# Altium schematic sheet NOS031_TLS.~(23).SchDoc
size A4
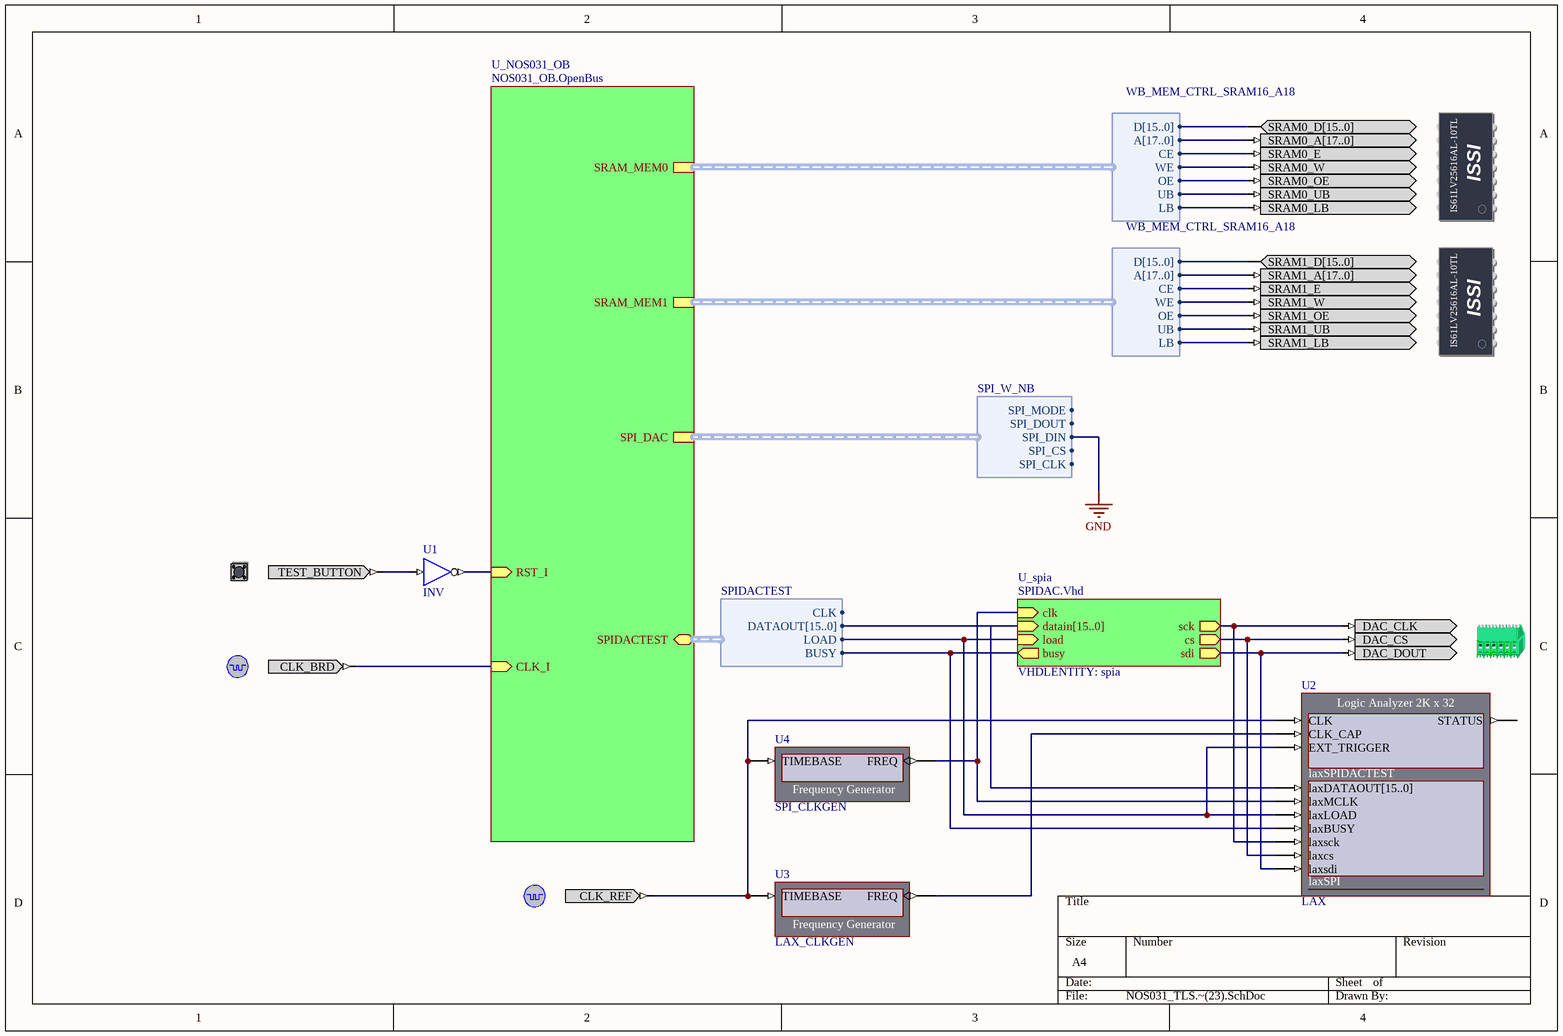
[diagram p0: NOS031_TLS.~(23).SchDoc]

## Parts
(Parts that share a designator on the sheet are numbered #1, #2 ... from top to bottom, then left to right.)
?#1  SRAM0  (value not drawn)
?#2  SRAM1  (value not drawn)
?#3  TEST_BUTTON  (value not drawn)
?#4  ADCDAC  (value not drawn)
?#5  CLOCK_BOARD  (value not drawn)
?#6  CLOCK_REFERENCE  (value not drawn)
U1  INV
U2  LAX
U3  LAX_CLKGEN
U4  SPI_CLKGEN

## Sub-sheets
U_NOS031_OB = NOS031_OB.OpenBus: SRAM_MEM0 (harness WB_MEM_CTRL_SRAM16_A18), SRAM_MEM1 (harness WB_MEM_CTRL_SRAM16_A18), SPI_DAC (harness SPI_W_NB), RST_I (in), CLK_I (in), SPIDACTEST (harness SPIDACTEST)
U_spia = SPIDAC.Vhd: busy (out), clk (in), cs (out), datain[15..0] (in), load (in), sck (out), sdi (out)  | VHDLENTITY: spia

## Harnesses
SPI_W_NB: SPI_CLK, SPI_CS, SPI_DIN, SPI_DOUT, SPI_MODE
WB_MEM_CTRL_SRAM16_A18: D[15..0], A[17..0], CE, WE, OE, UB, LB
SPIDACTEST: DATAOUT[15..0], LOAD, BUSY, CLK

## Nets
GND_BUS[9..0]: U2.Set0_Spare[9..0]
GND_BUS[31..0]: U2.Set1_Spare[31..0]
Net?#1_SRAM0_E: ?#1.SRAM0_E ; sheet U_NOS031_OB/SRAM_MEM0.CE
Net?#1_SRAM0_LB: ?#1.SRAM0_LB ; sheet U_NOS031_OB/SRAM_MEM0.LB
Net?#1_SRAM0_OE: ?#1.SRAM0_OE ; sheet U_NOS031_OB/SRAM_MEM0.OE
Net?#1_SRAM0_UB: ?#1.SRAM0_UB ; sheet U_NOS031_OB/SRAM_MEM0.UB
Net?#1_SRAM0_W: ?#1.SRAM0_W ; sheet U_NOS031_OB/SRAM_MEM0.WE
Net?#2_SRAM1_E: ?#2.SRAM1_E ; sheet U_NOS031_OB/SRAM_MEM1.CE
Net?#2_SRAM1_LB: ?#2.SRAM1_LB ; sheet U_NOS031_OB/SRAM_MEM1.LB
Net?#2_SRAM1_OE: ?#2.SRAM1_OE ; sheet U_NOS031_OB/SRAM_MEM1.OE
Net?#2_SRAM1_UB: ?#2.SRAM1_UB ; sheet U_NOS031_OB/SRAM_MEM1.UB
Net?#2_SRAM1_W: ?#2.SRAM1_W ; sheet U_NOS031_OB/SRAM_MEM1.WE
Net?#3_TEST_BUTTON: ?#3.TEST_BUTTON U1.I
Net?#4_DAC_CLK: ?#4.DAC_CLK U2.laxsck ; sheet U_spia/sck
Net?#4_DAC_CS: ?#4.DAC_CS U2.laxcs ; sheet U_spia/cs
Net?#4_DAC_DOUT: ?#4.DAC_DOUT U2.laxsdi ; sheet U_spia/sdi
Net?#5_CLK_BRD: ?#5.CLK_BRD ; sheet U_NOS031_OB/CLK_I
Net?#6_CLK_REF: ?#6.CLK_REF U2.CLK U3.TIMEBASE U4.TIMEBASE
NetU1_O: U1.O ; sheet U_NOS031_OB/RST_I
NetU2_CLK_CAP: U2.CLK_CAP U3.FREQ
NetU2_EXT_TRIGGER: U2.EXT_TRIGGER U2.laxLOAD ; sheet U_spia/load, sheet U_NOS031_OB/SPIDACTEST.LOAD
NetU2_laxBUSY: U2.laxBUSY ; sheet U_spia/busy, sheet U_NOS031_OB/SPIDACTEST.BUSY
NetU2_laxMCLK: U2.laxMCLK U4.FREQ ; sheet U_spia/clk

Not connected (* = marked no-connect by the designer): ?#1 SRAM0_A[17..0] SRAM0_D[15..0]; ?#2 SRAM1_A[17..0] SRAM1_D[15..0]; U2 laxDATAOUT[15..0] STATUS

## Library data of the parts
?#1 = SRAM0: Free Static RAM - Daughterboard; PortComponent: True
?#2 = SRAM1: Free Static RAM - Daughterboard; PortComponent: True
?#3 = TEST_BUTTON: Test / Reset Button; PortComponent: True
?#4 = DAC: Digital Analog Converter; PortComponent: True
?#5 = CLOCK_BOARD: Global System Clock Supply; PortComponent: True
?#6 = CLOCK_REFERENCE: Global System Clock Reference Supply; PortComponent: True
U1 = INV: Inverter; FunctionalClass: Logic Primitive; ArchiveName: GENERIC; VHDLIB_SIM: GENERIC_LIB
U2 = LAX: Configurable Logic Analyzer; NEXUS_CORE: Instrument; NEXUS_JTAG_DEVICE: True; NEXUS_JTAG_ORDER: 0; ConfiguratorName: LogicAnalyser; ConfigurationParameters: {}Version[1.0]{}CaptureWidth[32]{}MemorySize[2K]{}ExtAddrWidth[10]{}Set0[laxSPIDACTEST]{}Set0_Signal0[laxDATAOUT(15..0)]{}Style_Set0_Signal0[Default]{}Set0_Signal1[laxMCLK]{}Style_Set0_Signal1[Clock]{}Set0_Signal2[laxLOAD]{}Style_Set0_Signal2[Default]{}Set0_Signal3[laxBUSY]{}Style_Set0_Signal3[Default]{}Set0_Signal4[laxsck]{}Style_Set0_Signal4[Default]{}Set0_Signal5[laxcs]{}Style_Set0_Signal5[Default]{}Set0_Signal6[laxsdi]{}Style_Set0_Signal6[Default]{}Set1[laxSPI]{}ConnectSpareToGND[True]{}; ChildModel1: LAX_CFG32
U3 U4 = CLKGEN: Frequency Generator; NEXUS_CORE: Instrument; NEXUS_JTAG_DEVICE: True; NEXUS_JTAG_ORDER: 0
